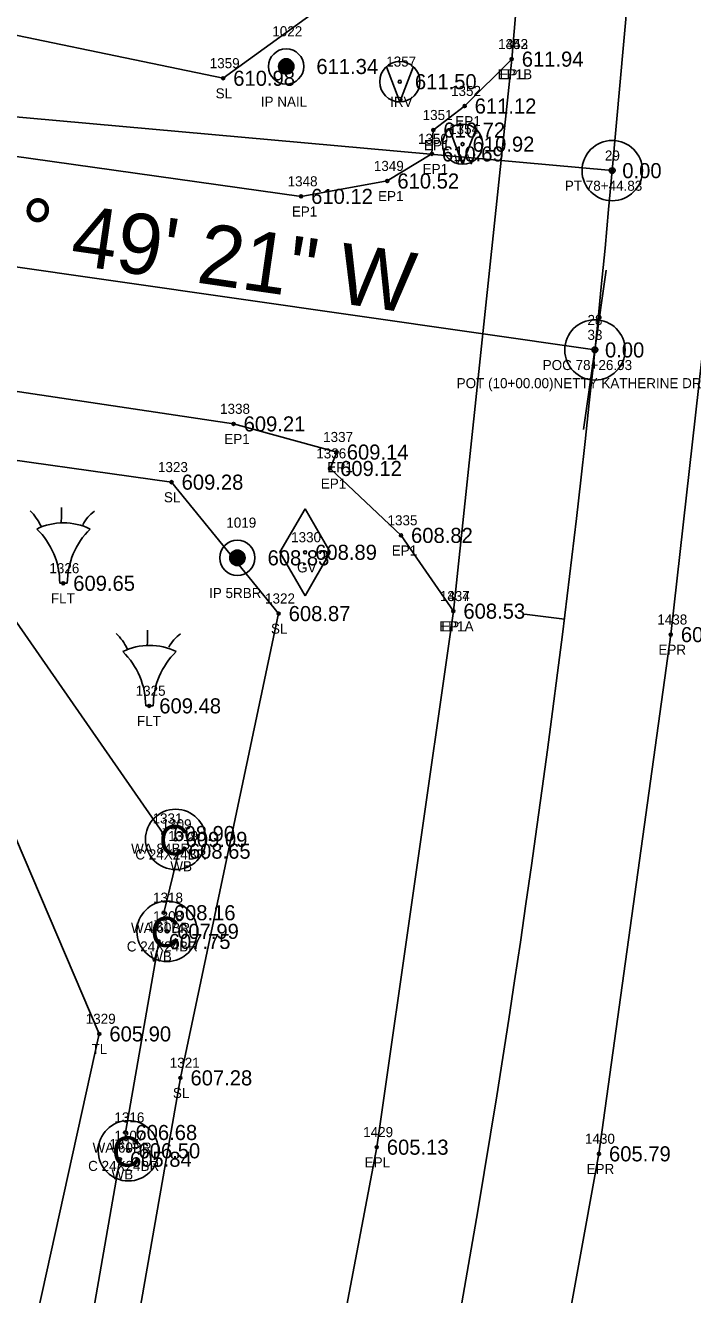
# Model space of a CAD drawing. Extents: x 1694813 to 1696862, y 1086485 to 1091027.
# Drawn here: x 1695772.2 to 1695838.5, y 1089855.4 to 1089981.5 of the extents above; entities that cross this region are included whole.
import ezdxf

# ---------------------------------------------------------------- set-up
doc = ezdxf.new("R2010")
doc.units = 0
for name, color, linetype in [('RD_EX_BldgApp', 7, 'Continuous'), ('RD_EX_BldgApp_txCode', 7, 'Continuous'), ('RD_EX_DV_Prop_txCode', 7, 'Continuous'), ('RD_EX_DV_PropPin', 7, 'Continuous'), ('RD_EX_Misc_txCode', 7, 'Continuous'), ('RD_EX_Road', 7, 'Continuous'), ('RD_EX_Road_txCode', 7, 'Continuous'), ('RD_EX_TX_BldgApp_ELEV', 7, 'Continuous'), ('RD_EX_TX_DV_Prop_ELEV', 7, 'Continuous'), ('RD_EX_TX_Misc_ELEV', 7, 'Continuous'), ('RD_EX_TX_Road_ELEV', 7, 'Continuous'), ('RD_EX_TX_UT_ELEV', 7, 'Continuous'), ('RD_EX_TX_VEG_ELEV', 7, 'Continuous'), ('RD_EX_UT', 7, 'Continuous'), ('RD_EX_UT_txCode', 7, 'Continuous'), ('RD_EX_VEG', 7, 'Continuous'), ('RD_EX_VEG_txCode', 7, 'Continuous'), ('RD_HC_Cl', 7, 'Continuous'), ('RD_HC_Data', 7, 'Continuous'), ('RD_HC_Data_Tic', 7, 'Continuous'), ('RD_HC_Survey_ELEV', 7, 'Continuous'), ('RD_HC_txCode', 7, 'Continuous'), ('RD_SMD_Locator', 7, 'Continuous')]:
    doc.layers.add(name, color=color, linetype=linetype)

msp = doc.modelspace()

# ---------------------------------------------------------------- linework, layer by layer
at = {"layer": 'RD_EX_BldgApp'}
for p, q in [((1695809.39, 1089973.92), (1695808.08, 1089977.41)), ((1695809.39, 1089973.92), (1695810.71, 1089977.37)), ((1695785.88, 1089901.2), (1695764.63, 1089931.79)), ((1695775.6, 1089926.08), (1695776.35, 1089926.08)), ((1695784.14, 1089913.9), (1695784.89, 1089913.9)), ((1695785.93, 1089893.33), (1695787.43, 1089899.45)), ((1695782.12, 1089871.49), (1695785.43, 1089890.48)), ((1695778.23, 1089849.69), (1695781.58, 1089868.83))]:
    msp.add_line(p, q, dxfattribs=at)
for centre, radius in [((1695809.39, 1089975.92), 2), ((1695809.39, 1089975.92), 0.15), ((1695787.11, 1089900.62), 3), ((1695786.26, 1089891.48), 3), ((1695782.42, 1089869.67), 3)]:
    msp.add_circle(centre, radius, dxfattribs=at)
for centre, radius, start, end in [((1695737.89, 1089933.42), 37.88, 358.0671, 0.2715), ((1695769.28, 1089929.73), 4.89, 24.3279, 46.2665), ((1695780.86, 1089930.48), 3.28, 123.2906, 154.4886), ((1695775.97, 1089926.08), 6, 63.7794, 116.2206), ((1695768.1, 1089926.08), 7.5, 0, 45.8366), ((1695783.85, 1089926.08), 7.5, 134.1634, 180), ((1695777.83, 1089917.55), 4.89, 24.3279, 46.2665), ((1695746.44, 1089921.24), 37.88, 358.0671, 0.2715), ((1695789.41, 1089918.3), 3.28, 123.2906, 154.4886), ((1695784.52, 1089913.9), 6, 63.7794, 116.2206), ((1695776.64, 1089913.9), 7.5, 0, 45.8366), ((1695792.39, 1089913.9), 7.5, 134.1634, 180)]:
    msp.add_arc(centre, radius, start, end, dxfattribs=at)
at = {"layer": 'RD_EX_DV_PropPin'}
for p, q in [((1695797.37, 1089977.23), (1695797.37, 1089977.62)), ((1695797.4, 1089977.13), (1695797.4, 1089977.72)), ((1695797.44, 1089977.06), (1695797.44, 1089977.8)), ((1695797.47, 1089977), (1695797.47, 1089977.85)), ((1695797.51, 1089976.95), (1695797.51, 1089977.9)), ((1695797.54, 1089976.91), (1695797.54, 1089977.94)), ((1695797.58, 1089976.87), (1695797.58, 1089977.98)), ((1695797.61, 1089976.84), (1695797.61, 1089978.01)), ((1695797.65, 1089976.82), (1695797.65, 1089978.04)), ((1695797.68, 1089976.79), (1695797.68, 1089978.06)), ((1695797.72, 1089976.77), (1695797.72, 1089978.08)), ((1695797.75, 1089976.75), (1695797.75, 1089978.1)), ((1695797.79, 1089976.73), (1695797.79, 1089978.12)), ((1695797.82, 1089976.72), (1695797.82, 1089978.13)), ((1695797.86, 1089976.71), (1695797.86, 1089978.15)), ((1695797.89, 1089976.69), (1695797.89, 1089978.16)), ((1695797.93, 1089976.68), (1695797.93, 1089978.17)), ((1695797.96, 1089976.68), (1695797.96, 1089978.17)), ((1695798, 1089976.67), (1695798, 1089978.18)), ((1695798.03, 1089976.67), (1695798.03, 1089978.18)), ((1695798.07, 1089976.67), (1695798.07, 1089978.19)), ((1695798.1, 1089976.66), (1695798.1, 1089978.19)), ((1695798.14, 1089976.67), (1695798.14, 1089978.19)), ((1695798.17, 1089976.67), (1695798.17, 1089978.18)), ((1695798.21, 1089976.67), (1695798.21, 1089978.18)), ((1695798.24, 1089976.68), (1695798.24, 1089978.17)), ((1695798.28, 1089976.68), (1695798.28, 1089978.17)), ((1695798.31, 1089976.69), (1695798.31, 1089978.16)), ((1695798.35, 1089976.71), (1695798.35, 1089978.15)), ((1695798.38, 1089976.72), (1695798.38, 1089978.13)), ((1695798.42, 1089976.73), (1695798.42, 1089978.12)), ((1695798.45, 1089976.75), (1695798.45, 1089978.1)), ((1695798.49, 1089976.77), (1695798.49, 1089978.08)), ((1695798.52, 1089976.79), (1695798.52, 1089978.06)), ((1695798.56, 1089976.82), (1695798.56, 1089978.04)), ((1695798.59, 1089976.84), (1695798.59, 1089978.01)), ((1695798.63, 1089976.87), (1695798.63, 1089977.98)), ((1695798.66, 1089976.91), (1695798.66, 1089977.94)), ((1695798.7, 1089976.95), (1695798.7, 1089977.9)), ((1695798.73, 1089977), (1695798.73, 1089977.85)), ((1695798.77, 1089977.06), (1695798.77, 1089977.8)), ((1695798.8, 1089977.13), (1695798.8, 1089977.72)), ((1695798.84, 1089977.23), (1695798.84, 1089977.62)), ((1695792.52, 1089928.41), (1695792.52, 1089928.8)), ((1695792.55, 1089928.3), (1695792.55, 1089928.9)), ((1695792.59, 1089928.23), (1695792.59, 1089928.97)), ((1695792.62, 1089928.18), (1695792.62, 1089929.03)), ((1695792.66, 1089928.13), (1695792.66, 1089929.08)), ((1695792.69, 1089928.09), (1695792.69, 1089929.12)), ((1695792.73, 1089928.05), (1695792.73, 1089929.15)), ((1695792.76, 1089928.02), (1695792.76, 1089929.18)), ((1695792.8, 1089927.99), (1695792.8, 1089929.21)), ((1695792.83, 1089927.97), (1695792.83, 1089929.24)), ((1695792.87, 1089927.95), (1695792.87, 1089929.26)), ((1695792.9, 1089927.93), (1695792.9, 1089929.28)), ((1695792.94, 1089927.91), (1695792.94, 1089929.3)), ((1695792.97, 1089927.89), (1695792.97, 1089929.31)), ((1695793.01, 1089927.88), (1695793.01, 1089929.32)), ((1695793.04, 1089927.87), (1695793.04, 1089929.33)), ((1695793.08, 1089927.86), (1695793.08, 1089929.34)), ((1695793.11, 1089927.85), (1695793.11, 1089929.35)), ((1695793.15, 1089927.85), (1695793.15, 1089929.36)), ((1695793.18, 1089927.84), (1695793.18, 1089929.36)), ((1695793.22, 1089927.84), (1695793.22, 1089929.36)), ((1695793.25, 1089927.84), (1695793.25, 1089929.36)), ((1695793.29, 1089927.84), (1695793.29, 1089929.36)), ((1695793.32, 1089927.84), (1695793.32, 1089929.36)), ((1695793.36, 1089927.85), (1695793.36, 1089929.36)), ((1695793.39, 1089927.85), (1695793.39, 1089929.35)), ((1695793.43, 1089927.86), (1695793.43, 1089929.34)), ((1695793.46, 1089927.87), (1695793.46, 1089929.33)), ((1695793.5, 1089927.88), (1695793.5, 1089929.32)), ((1695793.53, 1089927.89), (1695793.53, 1089929.31)), ((1695793.57, 1089927.91), (1695793.57, 1089929.3)), ((1695793.6, 1089927.93), (1695793.6, 1089929.28)), ((1695793.64, 1089927.95), (1695793.64, 1089929.26)), ((1695793.67, 1089927.97), (1695793.67, 1089929.24)), ((1695793.71, 1089927.99), (1695793.71, 1089929.21)), ((1695793.74, 1089928.02), (1695793.74, 1089929.18)), ((1695793.78, 1089928.05), (1695793.78, 1089929.15)), ((1695793.81, 1089928.09), (1695793.81, 1089929.12)), ((1695793.85, 1089928.13), (1695793.85, 1089929.08)), ((1695793.88, 1089928.18), (1695793.88, 1089929.03)), ((1695793.92, 1089928.23), (1695793.92, 1089928.97)), ((1695793.95, 1089928.3), (1695793.95, 1089928.9)), ((1695793.99, 1089928.41), (1695793.99, 1089928.8))]:
    msp.add_line(p, q, dxfattribs=at)
for centre, radius in [((1695798.1, 1089977.43), 1.75), ((1695798.1, 1089977.43), 0.761), ((1695793.25, 1089928.6), 1.75), ((1695793.25, 1089928.6), 0.761)]:
    msp.add_circle(centre, radius, dxfattribs=at)
at = {"layer": 'RD_EX_Road'}
for points in [[(1695813.78, 1089148.1), (1695805.56, 1089142.08), (1695776.44, 1089183.94), (1695749.27, 1089231.88), (1695730.49, 1089275.72), (1695714.87, 1089332.12), (1695707.87, 1089381.72), (1695706.58, 1089435.34), (1695711.58, 1089484.26), (1695722.15, 1089537.59), (1695749.04, 1089634.88), (1695776.11, 1089730.43), (1695788.13, 1089777.42), (1695798.89, 1089826.76), (1695807.1, 1089870.03), (1695814.71, 1089923.3), (1695820.51, 1089978.16), (1695824.04, 1090019.79), (1695832.76, 1090119.06), (1695841.25, 1090216.76), (1695850.36, 1090314.41), (1695859.24, 1090411.82), (1695868.09, 1090511.63), (1695876.75, 1090608.38)], [(1695735.35, 1089335.84), (1695728.69, 1089383.6), (1695727.9, 1089434.83), (1695732.68, 1089480.1), (1695743.4, 1089531.84), (1695770.35, 1089628.36), (1695797.63, 1089725.22), (1695809.49, 1089772.37), (1695818.34, 1089811.57), (1695820.65, 1089823.41), (1695822.99, 1089835.26), (1695829.18, 1089869.37), (1695836.32, 1089920.97), (1695842.44, 1089975.46), (1695846.49, 1090018.55), (1695849.32, 1090055.39), (1695850.91, 1090072.92), (1695855.09, 1090117.49), (1695863.53, 1090214.93), (1695872.56, 1090312.44), (1695881.69, 1090410.78), (1695890.45, 1090509.3), (1695899.01, 1090605.4)], [(1695733.94, 1089974.49), (1695752.2, 1089971.18), (1695799.58, 1089964.52), (1695808.15, 1089966.05), (1695812.58, 1089968.74), (1695812.72, 1089971.11), (1695815.83, 1089973.5), (1695820.51, 1089978.16)], [(1695814.71, 1089923.3), (1695809.51, 1089930.83), (1695802.46, 1089937.48), (1695803.12, 1089939.11), (1695792.87, 1089941.91), (1695747.41, 1089948.71), (1695731.33, 1089951.66)]]:
    msp.add_lwpolyline(points, dxfattribs=at)
at = {"layer": 'RD_EX_UT'}
for p, q in [((1695815.63, 1089967.72), (1695814.33, 1089971.2)), ((1695815.63, 1089967.72), (1695816.96, 1089971.16)), ((1695797.48, 1089929.15), (1695799.98, 1089933.48)), ((1695799.98, 1089933.48), (1695802.48, 1089929.15)), ((1695797.48, 1089929.15), (1695799.98, 1089924.82)), ((1695799.98, 1089924.82), (1695802.48, 1089929.15))]:
    msp.add_line(p, q, dxfattribs=at)
msp.add_circle((1695815.63, 1089969.71), 2, dxfattribs=at)
at = {"layer": 'RD_EX_VEG'}
for points in [[(1695762.44, 1089982.36), (1695791.84, 1089976.26), (1695804.67, 1089985.58), (1695805.61, 1090018.45), (1695818.68, 1090120.45), (1695830.78, 1090219.77), (1695838.1, 1090274.39)], [(1695703.52, 1089329.03), (1695695, 1089381.13), (1695696.39, 1089435.79), (1695702.88, 1089488.39), (1695714.38, 1089541.02), (1695736.44, 1089639.8), (1695727.2, 1089683.67), (1695743.97, 1089747.86), (1695756.74, 1089783.05), (1695766.78, 1089823.73), (1695779.53, 1089881.29), (1695754.55, 1089939.82)], [(1695775.83, 1089809.76), (1695787.59, 1089876.92), (1695797.35, 1089923.06), (1695786.71, 1089936.12), (1695764.52, 1089939.24)]]:
    msp.add_lwpolyline(points, dxfattribs=at)
at = {"layer": 'RD_HC_Cl'}
for p, q in [((1695830.5, 1089967.08), (1695888.3, 1090609.93)), ((1695828.78, 1089949.26), (1695732.64, 1089963.07))]:
    msp.add_line(p, q, dxfattribs=at)
msp.add_arc((1694493.64, 1090087.29), 1342.25, 344.31262, 354.86182, dxfattribs=at)
at = {"layer": 'RD_HC_Data'}
msp.add_line((1695830.5, 1089967.08), (1695715.49, 1089977.42), dxfattribs=at)
for centre, radius in [((1695830.5, 1089967.08), 3), ((1695830.5, 1089967.08), 0.282), ((1695828.78, 1089949.26), 3), ((1695828.78, 1089949.26), 3), ((1695828.78, 1089949.26), 0.282), ((1695828.78, 1089949.26), 0.282)]:
    msp.add_circle(centre, radius, dxfattribs=at)
at = {"layer": 'RD_HC_Data_Tic'}
for p, q in [((1695828.78, 1089949.26), (1695829.91, 1089957.18)), ((1695828.78, 1089949.26), (1695827.64, 1089941.34)), ((1695825.74, 1089922.5), (1695821.77, 1089922.99))]:
    msp.add_line(p, q, dxfattribs=at)
at = {"layer": 'RD_SMD_Locator'}
for centre in [(1695798.1, 1089977.43), (1695820.51, 1089978.16), (1695820.51, 1089978.16), (1695791.84, 1089976.26), (1695815.83, 1089973.5), (1695812.72, 1089971.11), (1695812.58, 1089968.74), (1695815.63, 1089969.71), (1695808.15, 1089966.05), (1695830.5, 1089967.08), (1695799.58, 1089964.52), (1695828.78, 1089949.26), (1695828.78, 1089949.26), (1695792.87, 1089941.91), (1695803.12, 1089939.11), (1695802.46, 1089937.48), (1695786.71, 1089936.12), (1695809.51, 1089930.83), (1695793.25, 1089928.6), (1695799.98, 1089929.15), (1695775.94, 1089926.07), (1695814.71, 1089923.3), (1695814.71, 1089923.3), (1695797.35, 1089923.06), (1695836.32, 1089920.97), (1695784.49, 1089913.89), (1695785.88, 1089901.2), (1695787.11, 1089900.62), (1695787.43, 1089899.45), (1695785.93, 1089893.33), (1695785.43, 1089890.48), (1695786.26, 1089891.48), (1695779.53, 1089881.29), (1695787.59, 1089876.92), (1695782.12, 1089871.49), (1695782.42, 1089869.67), (1695807.1, 1089870.03), (1695829.18, 1089869.37), (1695781.58, 1089868.83)]:
    msp.add_circle(centre, 0.15, dxfattribs=at)

# ---------------------------------------------------------------- texts
at = {"layer": 'RD_EX_BldgApp'}
for p in [(1695785.48, 1089899.05), (1695784.63, 1089889.92), (1695780.79, 1089868.1)]:
    msp.add_text('C', height=3, dxfattribs=at).set_placement(p)
at = {"layer": 'RD_EX_BldgApp_txCode'}
for s, p in [('1326', (1695774.57, 1089927.07)), ('FLT', (1695774.72, 1089924.07)), ('1325', (1695783.14, 1089914.89)), ('FLT', (1695783.27, 1089911.89)), ('1309', (1695785.72, 1089901.62)), ('C 24X24BR', (1695783.11, 1089898.62)), ('1308', (1695784.88, 1089892.48)), ('C 24X24BR', (1695782.26, 1089889.48)), ('1307', (1695781.03, 1089870.67)), ('C 24X24BR', (1695778.42, 1089867.67))]:
    msp.add_text(s, height=1, dxfattribs=at).set_placement(p)
at = {"layer": 'RD_EX_DV_Prop_txCode'}
for s, p in [('1022', (1695796.72, 1089980.43)), ('IP NAIL', (1695795.58, 1089973.43)), ('1019', (1695792.15, 1089931.6)), ('IP 5RBR', (1695790.44, 1089924.6))]:
    msp.add_text(s, height=1, dxfattribs=at).set_placement(p)
at = {"layer": 'RD_EX_Misc_txCode'}
for s, p in [('1357', (1695808.04, 1089977.42)), ('IRV', (1695808.43, 1089973.42)), ('1331', (1695784.82, 1089902.2)), ('1319', (1695786.37, 1089900.45)), ('WA 84BR', (1695782.69, 1089899.2)), ('WB', (1695786.59, 1089897.45)), ('1318', (1695784.87, 1089894.33)), ('WA 60BR', (1695782.68, 1089891.33)), ('1317', (1695784.36, 1089891.48)), ('WB', (1695784.58, 1089888.48)), ('1316', (1695781.03, 1089872.49)), ('WA 60BR', (1695778.86, 1089869.49)), ('1315', (1695780.52, 1089869.83)), ('WB', (1695780.74, 1089866.83))]:
    msp.add_text(s, height=1, dxfattribs=at).set_placement(p)
at = {"layer": 'RD_EX_Road_txCode'}
for s, p in [('1353', (1695819.16, 1089979.16)), ('1442', (1695819.16, 1089979.16)), ('EP1B', (1695819.12, 1089976.16)), ('EPL', (1695819.31, 1089976.16)), ('1352', (1695814.48, 1089974.5)), ('1351', (1695811.66, 1089972.11)), ('EP1', (1695814.91, 1089971.5)), ('1350', (1695811.2, 1089969.74)), ('EP1', (1695811.8, 1089969.11)), ('1349', (1695806.81, 1089967.05)), ('EP1', (1695811.66, 1089966.74)), ('1348', (1695798.24, 1089965.52)), ('EP1', (1695807.23, 1089964.05)), ('EP1', (1695798.66, 1089962.52)), ('1338', (1695791.53, 1089942.91)), ('1337', (1695801.77, 1089940.11)), ('EP1', (1695791.95, 1089939.91)), ('1336', (1695801.09, 1089938.48)), ('EP1', (1695802.19, 1089937.11)), ('EP1', (1695801.54, 1089935.48)), ('1335', (1695808.17, 1089931.83)), ('EP1', (1695808.59, 1089928.83)), ('1334', (1695813.37, 1089924.3)), ('1437', (1695813.37, 1089924.3)), ('EP1A', (1695813.3, 1089921.3)), ('EPL', (1695813.51, 1089921.3)), ('1438', (1695834.98, 1089921.97)), ('EPR', (1695835.09, 1089918.97)), ('1429', (1695805.75, 1089871.03)), ('1430', (1695827.79, 1089870.37)), ('EPL', (1695805.9, 1089868.03)), ('EPR', (1695827.95, 1089867.37))]:
    msp.add_text(s, height=1, dxfattribs=at).set_placement(p)
at = {"layer": 'RD_EX_TX_BldgApp_ELEV'}
for s, p in [('609.65', (1695776.94, 1089925.32)), ('609.48', (1695785.49, 1089913.14)), ('609.09', (1695788.11, 1089899.87)), ('607.99', (1695787.26, 1089890.73)), ('606.50', (1695783.42, 1089868.92))]:
    msp.add_text(s, height=1.5, dxfattribs=at).set_placement(p)
at = {"layer": 'RD_EX_TX_DV_Prop_ELEV'}
for s, p in [('611.34', (1695801.1, 1089976.68)), ('608.83', (1695796.25, 1089927.85))]:
    msp.add_text(s, height=1.5, dxfattribs=at).set_placement(p)
at = {"layer": 'RD_EX_TX_Misc_ELEV'}
for s, p in [('611.50', (1695810.89, 1089975.17)), ('608.90', (1695786.88, 1089900.45)), ('608.65', (1695788.43, 1089898.7)), ('608.16', (1695786.93, 1089892.58)), ('607.75', (1695786.43, 1089889.73)), ('606.68', (1695783.12, 1089870.74)), ('605.84', (1695782.58, 1089868.08))]:
    msp.add_text(s, height=1.5, dxfattribs=at).set_placement(p)
at = {"layer": 'RD_EX_TX_Road_ELEV'}
for s, p in [('611.94', (1695821.51, 1089977.41)), ('611.94', (1695821.51, 1089977.41)), ('611.12', (1695816.83, 1089972.75)), ('610.72', (1695813.72, 1089970.36)), ('610.69', (1695813.58, 1089967.99)), ('610.52', (1695809.15, 1089965.3)), ('610.12', (1695800.58, 1089963.77)), ('609.21', (1695793.87, 1089941.16)), ('609.14', (1695804.12, 1089938.36)), ('609.12', (1695803.46, 1089936.73)), ('608.82', (1695810.51, 1089930.08)), ('608.53', (1695815.71, 1089922.55)), ('608.53', (1695815.71, 1089922.55)), ('608.79', (1695837.32, 1089920.22)), ('605.13', (1695808.1, 1089869.28)), ('605.79', (1695830.18, 1089868.62))]:
    msp.add_text(s, height=1.5, dxfattribs=at).set_placement(p)
at = {"layer": 'RD_EX_TX_UT_ELEV'}
for s, p in [('610.92', (1695816.63, 1089968.96)), ('608.89', (1695800.98, 1089928.4))]:
    msp.add_text(s, height=1.5, dxfattribs=at).set_placement(p)
at = {"layer": 'RD_EX_TX_VEG_ELEV'}
for s, p in [('610.98', (1695792.84, 1089975.51)), ('609.28', (1695787.71, 1089935.37)), ('608.87', (1695798.35, 1089922.31)), ('605.90', (1695780.53, 1089880.54)), ('607.28', (1695788.59, 1089876.17))]:
    msp.add_text(s, height=1.5, dxfattribs=at).set_placement(p)
at = {"layer": 'RD_EX_UT_txCode'}
for s, p in [('1354', (1695814.29, 1089970.71)), ('WV', (1695814.78, 1089967.71)), ('1330', (1695798.59, 1089930.15)), ('GV', (1695799.18, 1089927.15))]:
    msp.add_text(s, height=1, dxfattribs=at).set_placement(p)
at = {"layer": 'RD_EX_VEG_txCode'}
for s, p in [('1359', (1695790.5, 1089977.26)), ('SL', (1695791.09, 1089974.26)), ('1323', (1695785.36, 1089937.12)), ('SL', (1695785.95, 1089934.12)), ('1322', (1695796, 1089924.06)), ('SL', (1695796.59, 1089921.06)), ('1329', (1695778.18, 1089882.29)), ('TL', (1695778.76, 1089879.29)), ('1321', (1695786.53, 1089877.92)), ('SL', (1695786.84, 1089874.92))]:
    msp.add_text(s, height=1, dxfattribs=at).set_placement(p)
at = {"layer": 'RD_HC_Data'}
msp.add_text('N 81%%d 49\' 21" W', height=6, rotation=351.8225, dxfattribs=at).set_placement((1695754.36, 1089960.96))
at = {"layer": 'RD_HC_Survey_ELEV'}
for p in [(1695831.5, 1089966.33), (1695829.78, 1089948.51), (1695829.78, 1089948.51)]:
    msp.add_text('0.00', height=1.5, dxfattribs=at).set_placement(p)
at = {"layer": 'RD_HC_txCode'}
for s, p in [('29', (1695829.77, 1089968.08)), ('PT 78+44.83', (1695825.79, 1089965.08)), ('28', (1695828.04, 1089951.74)), ('33', (1695828.04, 1089950.26)), ('POC 78+26.93', (1695823.59, 1089947.26)), ('POT (10+00.00)NETTY KATHERINE DR', (1695815.04, 1089945.46))]:
    msp.add_text(s, height=1, dxfattribs=at).set_placement(p)

doc.saveas('drawing.dxf')
